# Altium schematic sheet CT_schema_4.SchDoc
size 288 x 169 mm
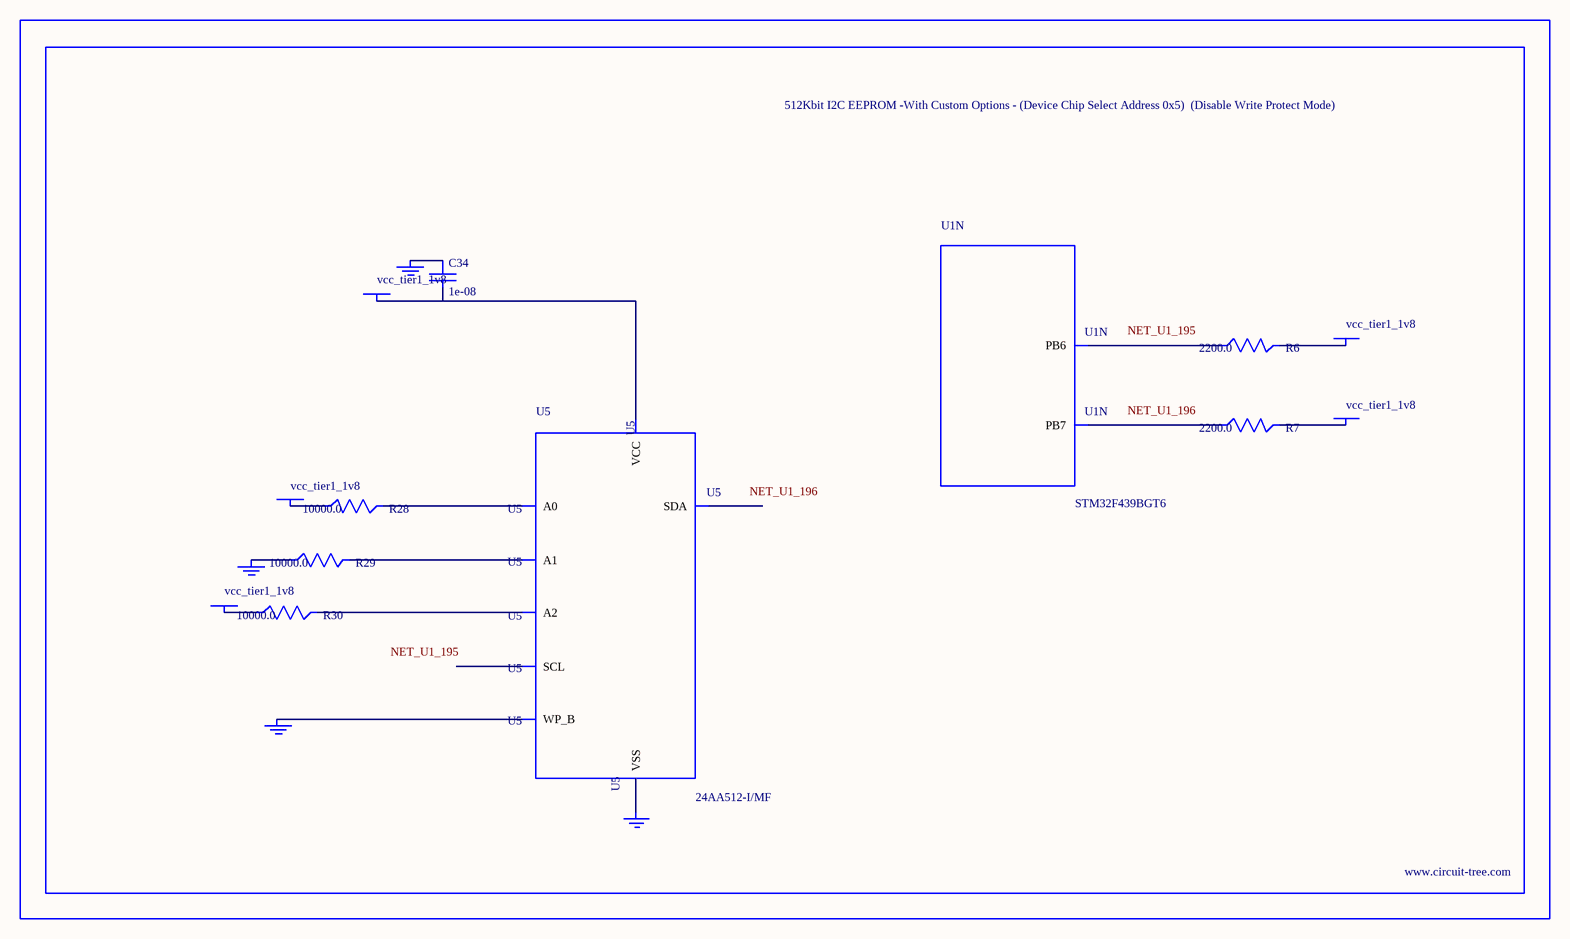
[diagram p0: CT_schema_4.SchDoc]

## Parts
BORDER3  (no value)
C34  1e-08  [C0402]
GND_INSTANCE_3_0  (no value)
GND_INSTANCE_3_1  (no value)
GND_INSTANCE_3_2  (no value)
GND_INSTANCE_3_3  (no value)
POWER_INSTANCE_3_0  vcc_tier1_1v8
POWER_INSTANCE_3_1  vcc_tier1_1v8
POWER_INSTANCE_3_2  vcc_tier1_1v8
POWER_INSTANCE_3_3  vcc_tier1_1v8
POWER_INSTANCE_3_4  vcc_tier1_1v8
R6  2200.0  [R0603]
R7  2200.0  [R0603]
R28  10000.0  [R0603]
R29  10000.0  [R0603]
R30  10000.0  [R0603]
U1  STM32F439BGT6  [LQFP208]  (part N of 18)
U5  24AA512-I/MF  [DFN8-S]

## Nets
NetC34_1: C34.1 GND_INSTANCE_3_2.0(GND)
NetC34_2: C34.2 POWER_INSTANCE_3_2.0(PWR) U5.8(VCC)
NetGND_INSTANCE_3_0_0: GND_INSTANCE_3_0.0(GND) R29.1
NetGND_INSTANCE_3_1_0: GND_INSTANCE_3_1.0(GND) U5.7(WP_B)
NetGND_INSTANCE_3_3_0: GND_INSTANCE_3_3.0(GND) U5.4(VSS)
NetPOWER_INSTANCE_3_0_0: POWER_INSTANCE_3_0.0(PWR) R28.1
NetPOWER_INSTANCE_3_1_0: POWER_INSTANCE_3_1.0(PWR) R30.1
NetPOWER_INSTANCE_3_3_0: POWER_INSTANCE_3_3.0(PWR) R6.2
NetPOWER_INSTANCE_3_4_0: POWER_INSTANCE_3_4.0(PWR) R7.2
NetR6_1: R6.1 U1.195(PB6)
NetR7_1: R7.1 U1.196(PB7)
NetR28_2: R28.2 U5.1(A0)
NetR29_2: R29.2 U5.2(A1)
NetR30_2: R30.2 U5.3(A2)

Not connected (* = marked no-connect by the designer): U5 5(SDA) 6(SCL)

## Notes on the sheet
- Labels drawn without touching a wire or pin: NET_U1_195, NET_U1_196

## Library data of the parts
BORDER3 = BORDER_PAGE3
C34 = C0402C103K3RAC
GND_INSTANCE_3_0-GND_INSTANCE_3_3 = GND
POWER_INSTANCE_3_0-POWER_INSTANCE_3_4 = PWR
R6 R7 = RC0603JR-072K2L
R28-R30 = RC0603JR-0710KL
